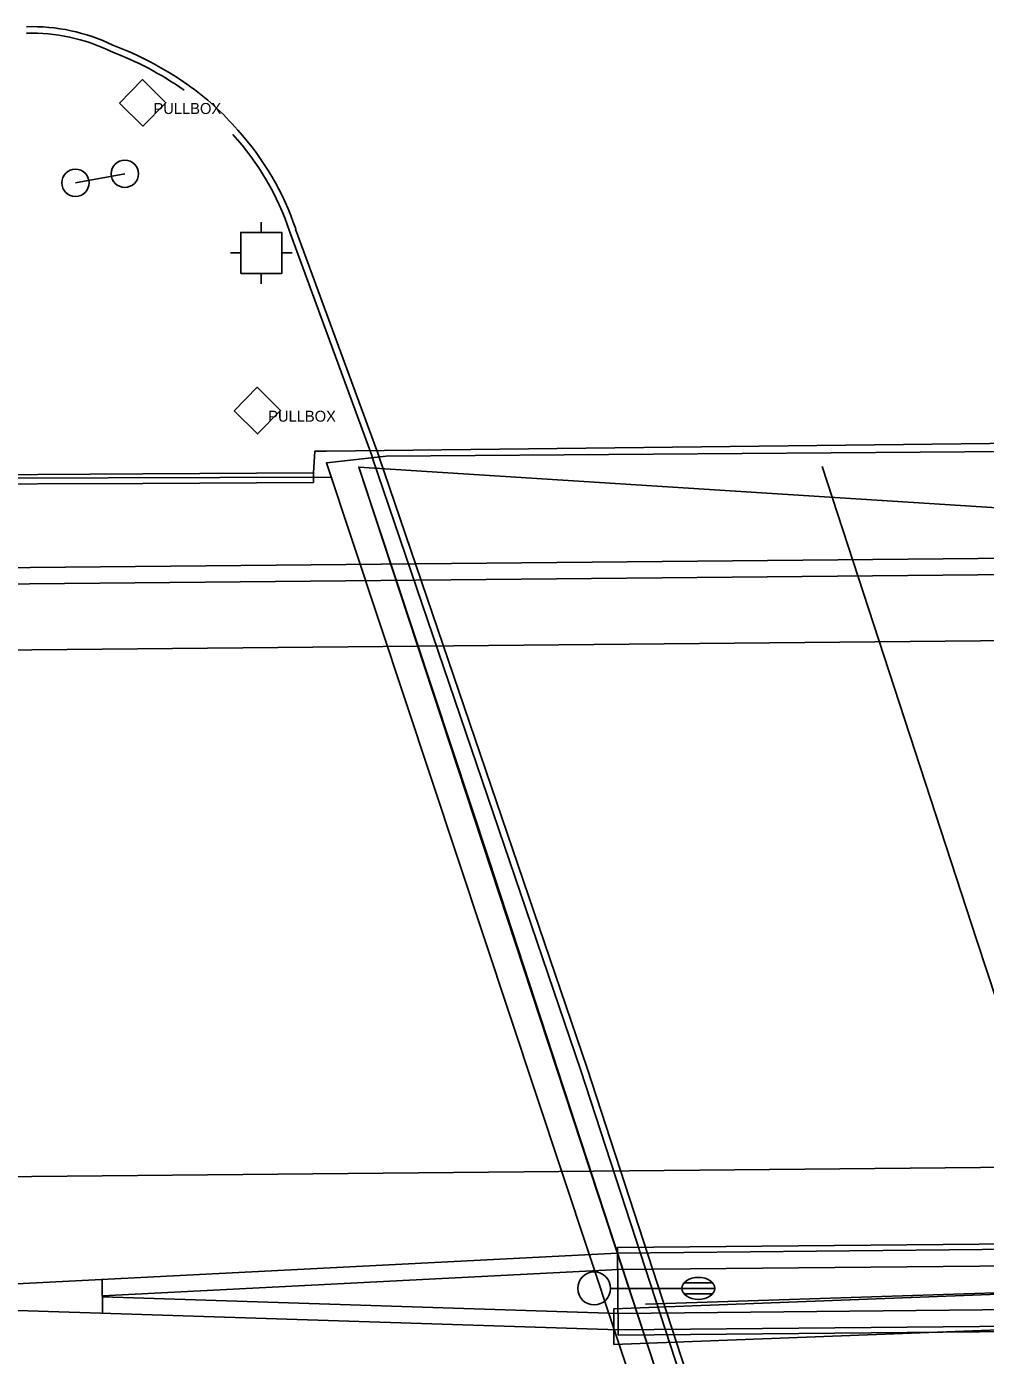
# Model space of a CAD drawing. Extents: x 2145380 to 2157287, y 139568 to 149130.
# Drawn here: x 2147239.5 to 2147326.9, y 143054.1 to 143175.2 of the extents above; entities that cross this region are included whole.
import ezdxf

# ---------------------------------------------------------------- set-up
doc = ezdxf.new("R2010")
doc.units = 0
for name, color, linetype in [('Default', 7, 'Continuous'), ('PR_PREVIOUSLY CONSTRUCTED', 7, 'Continuous'), ('TOPO_Asphalt', 7, 'Continuous'), ('TOPO_Bridge', 7, 'Continuous'), ('TOPO_BRIDGE_Floor Deck', 7, 'Continuous'), ('TOPO_BRIDGE_Low Beam', 7, 'Continuous'), ('TOPO_BRIDGE_Pier', 7, 'Continuous'), ('TOPO_BRIDGE_Pier Cap', 7, 'Continuous'), ('TOPO_Curb Back', 7, 'Continuous'), ('TOPO_Light Pole', 7, 'Continuous'), ('TOPO_Misc', 7, 'Continuous'), ('TOPO_Misc Line', 7, 'Continuous'), ('TOPO_Power Pullbox', 7, 'Continuous'), ('TOPO_Sign', 7, 'Continuous'), ('TOPO_Traffic Signal', 7, 'Continuous'), ('TOPO_Wall Freestanding', 7, 'Continuous')]:
    doc.layers.add(name, color=color, linetype=linetype)

# ---------------------------------------------------------------- blocks, each defined once
blk = doc.blocks.new('POST')
at = {"layer": 'TOPO_Misc'}
for start, end in [(90, 180), (360, 90), (180, 270), (270, 0)]:
    blk.add_arc((-0.01, 0.03), 3.16, start, end, dxfattribs=at)
blk = doc.blocks.new('TRFSIG')
at = {"layer": 'TOPO_Traffic Signal'}
for p, q in [((0.04, 4.66), (0.04, 7.04)), ((-4.7, -0.09), (-7.08, -0.09)), ((4.79, -0.09), (7.17, -0.09)), ((0.04, -4.83), (0.04, -7.22))]:
    blk.add_line(p, q, dxfattribs=at)
blk.add_lwpolyline([(-4.7, -4.85), (4.81, -4.83), (4.79, 4.67), (-4.72, 4.66), (-4.7, -4.85)], dxfattribs=at)
blk = doc.blocks.new('LP')
at = {"layer": 'TOPO_Light Pole'}
blk.add_line((3.81, 0), (20.32, 0), dxfattribs=at)
for points in [[(20.32, 0), (27.94, 0)], [(20.32, 0), (23.5, 0)], [(20.83, 1.27), (27.43, 1.27)], [(20.83, 1.27), (23.5, 1.27)], [(23.71, 1.27), (27.43, 1.27)], [(23.71, 0), (27.94, 0)], [(20.83, -1.27), (27.43, -1.27)], [(20.83, -1.27), (23.5, -1.27)], [(23.71, -1.27), (27.43, -1.27)]]:
    blk.add_lwpolyline(points, dxfattribs=at)
blk.add_circle((0, 0), 3.81, dxfattribs=at)
blk.add_ellipse((24.13, 0), major_axis=(3.81, 0), ratio=0.666667, dxfattribs=at)
blk = doc.blocks.new('pulbox')
at = {"layer": 'Default'}
blk.add_lwpolyline([(-5.38, -0.01), (-0.02, 5.42), (5.4, 0.06), (0.05, -5.36), (-5.38, -0.01)], dxfattribs=at)
blk.add_text('PULLBOX', height=2.54, dxfattribs=at).set_placement((2.54, -2.54))

msp = doc.modelspace()

# ---------------------------------------------------------------- linework, layer by layer
at = {"layer": 'PR_PREVIOUSLY CONSTRUCTED'}
for p, q in [((2146746.76, 143113.71), (2147732.05, 143123.05)), ((2146353.97, 143061.98), (2147732.51, 143075.05)), ((2147293.38, 143063.89), (2147410.04, 143064.99)), ((2147293.38, 143063.39), (2147410.04, 143064.49)), ((2147293.45, 143055.89), (2147293.38, 143063.89)), ((2147234.91, 143060.39), (2147293.38, 143063.39)), ((2147293.4, 143061.89), (2147410.06, 143062.99)), ((2147246.42, 143059.48), (2147293.46, 143061.89)), ((2147246.43, 143057.9), (2147246.4, 143060.98)), ((2147246.42, 143059.4), (2147293.5, 143057.89)), ((2147293.44, 143057.89), (2147410.1, 143058.99)), ((2147234.93, 143058.27), (2147293.45, 143056.39)), ((2147293.45, 143056.39), (2147410.11, 143057.49)), ((2147293.45, 143055.89), (2147410.12, 143056.99))]:
    msp.add_line(p, q, dxfattribs=at)
for points in [[(2146746.61, 143129.21), (2147125.89, 143132.8), (2147166.18, 143125.18), (2147422.32, 143127.61), (2147722.25, 143136.46), (2147731.92, 143136.55)], [(2146746.63, 143127.71), (2147125.75, 143131.3), (2147166.04, 143123.68), (2147422.35, 143126.11), (2147722.28, 143134.96), (2147731.94, 143135.05)]]:
    msp.add_lwpolyline(points, dxfattribs=at)
at = {"layer": 'TOPO_Asphalt'}
msp.add_arc((2147240.35, 143150.04), 24.19, 40.4721, 55.1612, dxfattribs=at)
at = {"layer": 'TOPO_Bridge'}
for points in [[(2147266.84, 143136.47), (2147385.2, 143137.85)], [(2147266.84, 143136.47), (2147265.77, 143136.48), (2147265.66, 143134.52), (2147265.67, 143133.62)]]:
    msp.add_lwpolyline(points, dxfattribs=at)
at = {"layer": 'TOPO_BRIDGE_Floor Deck'}
msp.add_lwpolyline([(2147436.61, 142985.9), (2147430.94, 142985.14), (2147374.14, 142984.81), (2147321.86, 142984.22), (2147317.02, 142984.28), (2147266.83, 143135.41), (2147272.28, 143136.04), (2147329.08, 143136.44), (2147381.28, 143136.94), (2147386.15, 143136.73), (2147400.2, 143094.81)], close=True, dxfattribs=at)
at = {"layer": 'TOPO_BRIDGE_Low Beam'}
msp.add_lwpolyline([(2147315.63, 142995.71), (2147304.21, 143030.31), (2147281.68, 143099.17), (2147269.78, 143135.04)], dxfattribs=at)
for points in [[(2147269.78, 143135.04), (2147269.78, 143135.04), (2147281.68, 143099.17), (2147304.21, 143030.31), (2147315.63, 142995.71), (2147315.63, 142995.71)], [(2147269.78, 143135.04), (2147269.78, 143135.04), (2147386.2, 143127.6), (2147386.2, 143127.6)], [(2147386.2, 143127.6), (2147269.78, 143135.04), (2147281.68, 143099.17), (2147304.21, 143030.31), (2147315.63, 142995.71), (2147432.69, 142986.37), (2147415.55, 143038.12), (2147399.9, 143086.04)], [(2147269.78, 143135.04), (2147386.2, 143127.6), (2147432.69, 142986.37), (2147315.63, 142995.71)]]:
    msp.add_lwpolyline(points, close=True, dxfattribs=at)
at = {"layer": 'TOPO_BRIDGE_Pier'}
for p, q in [((2147406.71, 143062.35), (2147295.93, 143058.72)), ((2147293.03, 143058.29), (2147293.03, 143058.29)), ((2147293.05, 143055.06), (2147293.05, 143055.06))]:
    msp.add_line(p, q, dxfattribs=at)
msp.add_lwpolyline([(2147293.05, 143055.06), (2147409.54, 143059.5), (2147409.53, 143062.73), (2147293.03, 143058.29)], close=True, dxfattribs=at)
msp.add_lwpolyline([(2147293.05, 143055.06), (2147409.54, 143059.5), (2147409.53, 143062.73), (2147293.03, 143058.29)], close=True, dxfattribs=at)
at = {"layer": 'TOPO_BRIDGE_Pier Cap'}
msp.add_lwpolyline([(2147409.54, 143059.5), (2147409.53, 143062.73), (2147293.03, 143058.29)], dxfattribs=at)
at = {"layer": 'TOPO_Curb Back'}
for points in [[(2147263.46, 143156.53), (2147270.97, 143136.09), (2147271.03, 143135.9)], [(2147264.03, 143156.73), (2147271.53, 143136.29), (2147271.64, 143135.97)], [(2147321.3, 142984.13), (2147290.03, 143080.04), (2147271.05, 143135.84)], [(2147321.87, 142984.32), (2147290.6, 143080.23), (2147271.62, 143136.03)]]:
    msp.add_lwpolyline(points, dxfattribs=at)
for centre, radius, start, end in [((2147240.02, 143158.37), 16.81, 64.0732, 91.8459), ((2147240.02, 143158.37), 16.21, 63.9748, 91.8615), ((2147236.65, 143144.96), 29.88, 54.8589, 69.4632), ((2147236.65, 143144.96), 30.48, 54.8589, 69.4093), ((2147240.26, 143148.84), 25.05, 18.3724, 42.4234), ((2147240.26, 143148.84), 24.45, 18.3505, 42.4234)]:
    msp.add_arc(centre, radius, start, end, dxfattribs=at)
at = {"layer": 'TOPO_Misc Line'}
msp.add_lwpolyline([(2147360.77, 142986.89), (2147326.16, 143091.87), (2147312.04, 143135.08)], dxfattribs=at)
at = {"layer": 'TOPO_Sign'}
msp.add_lwpolyline([(2147248.46, 143161.76), (2147243.95, 143160.93)], dxfattribs=at)
at = {"layer": 'TOPO_Wall Freestanding'}
msp.add_line((2147267.26, 143134.11), (2147230.71, 143133.99), dxfattribs=at)
for points in [[(2147265.66, 143134.52), (2147250.08, 143134.42), (2147230.89, 143134.3), (2147230.89, 143133.49)], [(2147265.67, 143133.62), (2147250.1, 143133.54), (2147230.89, 143133.49)]]:
    msp.add_lwpolyline(points, dxfattribs=at)

# ---------------------------------------------------------------- block references
at = {"layer": 'TOPO_Light Pole', "xscale": 0.39370000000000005, "yscale": 0.3937000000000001}
msp.add_blockref('LP', (2147291.25, 143060.17), dxfattribs=at)
at = {"layer": 'TOPO_Misc', "xscale": 0.39370000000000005, "yscale": 0.3937000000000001}
for p in [(2147243.95, 143160.93), (2147248.46, 143161.76)]:
    msp.add_blockref('POST', p, dxfattribs=at)
at = {"layer": 'TOPO_Power Pullbox', "xscale": 0.39370000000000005, "yscale": 0.3937000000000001}
for p in [(2147250.07, 143168.22), (2147260.53, 143140.17)]:
    msp.add_blockref('pulbox', p, dxfattribs=at)
at = {"layer": 'TOPO_Traffic Signal', "xscale": 0.39370000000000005, "yscale": 0.3937000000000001}
msp.add_blockref('TRFSIG', (2147260.88, 143154.59), dxfattribs=at)

doc.saveas('drawing.dxf')
